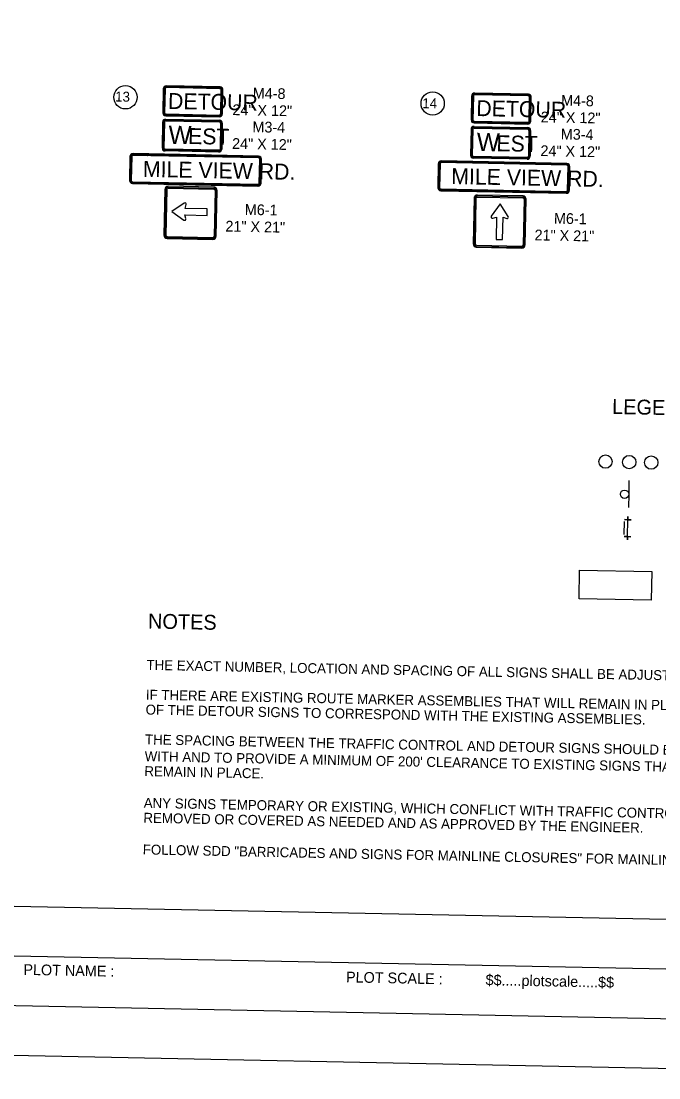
# Model space of a CAD drawing. Extents: x 299354 to 1325680, y 96128 to 228242.
# Drawn here: x 1319839 to 1323046, y 143563 to 148877 of the extents above; entities that cross this region are included whole.
import ezdxf

# ---------------------------------------------------------------- set-up
doc = ezdxf.new("R2010")
doc.units = 0
for name, color, linetype in [('CA-TEXT', 7, 'Continuous'), ('CE-TOPO-CONC-SLAB', 7, 'Continuous'), ('P_SGN_Cell', 7, 'Continuous'), ('P_TC', 7, 'Continuous'), ('PLT_Sheet_Border', 7, 'Continuous'), ('PLT_Sheet_Info', 7, 'Continuous'), ('SIGNS-POLES', 7, 'Continuous')]:
    doc.layers.add(name, color=color, linetype=linetype)

msp = doc.modelspace()

# ---------------------------------------------------------------- linework, layer by layer
at = {"layer": 'CA-TEXT'}
for centre in [(1320363.6, 148494.5), (1321908.5, 148463.4)]:
    msp.add_circle(centre, 58.6, dxfattribs=at)
at = {"layer": 'CE-TOPO-CONC-SLAB'}
for centre in [(1322777.7, 146662.3), (1322897, 146659.9), (1323007.6, 146657.6)]:
    msp.add_circle(centre, 33.5, dxfattribs=at)
at = {"layer": 'P_SGN_Cell'}
for p, q in [((1320565.7, 148384.6), (1320835.9, 148379.2)), ((1320565.9, 148380.9), (1320835.8, 148375.4)), ((1320550.6, 148369.9), (1320548, 148240)), ((1320554.4, 148369.9), (1320551.8, 148239.9)), ((1320559.4, 148369.8), (1320556.8, 148239.8)), ((1320565.8, 148375.9), (1320835.7, 148370.4)), ((1320841.8, 148364.1), (1320839.2, 148234.1)), ((1320846.8, 148364), (1320844.2, 148234)), ((1320850.6, 148363.9), (1320847.9, 148233.9)), ((1322101.4, 148333.7), (1322098.7, 148203.7)), ((1322105.1, 148333.6), (1322102.5, 148203.6)), ((1322110.1, 148333.5), (1322107.5, 148203.5)), ((1322116.5, 148348.4), (1322386.6, 148343)), ((1322116.5, 148339.6), (1322386.4, 148334.2)), ((1322116.6, 148344.6), (1322386.5, 148339.2)), ((1322392.5, 148327.8), (1322389.9, 148197.9)), ((1322397.5, 148327.7), (1322394.9, 148197.8)), ((1322401.3, 148327.7), (1322398.7, 148197.7)), ((1320832.7, 148219.2), (1320562.7, 148224.7)), ((1320832.7, 148223), (1320562.8, 148228.4)), ((1320832.8, 148228), (1320562.9, 148233.4)), ((1322383.4, 148183), (1322113.4, 148188.4)), ((1322383.5, 148186.7), (1322113.5, 148192.2)), ((1322383.6, 148191.7), (1322113.6, 148197.2)), ((1320561.8, 148031), (1320557.2, 147801.4)), ((1320566.2, 148030.9), (1320561.5, 147801.3)), ((1320571.6, 148030.8), (1320567, 147801.2)), ((1320578.3, 148037.3), (1320808, 148032.6)), ((1320578.4, 148042.7), (1320808.1, 148038.1)), ((1320808.2, 148042.5), (1320578.5, 148047.1)), ((1320814.4, 148025.9), (1320809.8, 147796.3)), ((1320819.9, 148025.8), (1320815.2, 147796.2)), ((1320819.6, 147796.1), (1320824.2, 148025.7)), ((1320659.2, 147962.1), (1320596.5, 147920.8)), ((1320663, 147935.9), (1320669.1, 147954.6)), ((1322116.5, 147986.7), (1322111.9, 147757.1)), ((1322120.9, 147986.7), (1322116.3, 147757)), ((1322126.4, 147986.5), (1322121.7, 147756.9)), ((1322133.1, 147993), (1322362.7, 147988.4)), ((1322133.2, 147998.4), (1322362.8, 147993.8)), ((1322362.9, 147998.2), (1322133.3, 148002.8)), ((1322247.2, 147957.9), (1322203.4, 147896.8)), ((1322288.6, 147895.1), (1322247.2, 147957.9)), ((1322369.1, 147981.7), (1322364.5, 147752)), ((1322374.6, 147981.5), (1322370, 147751.9)), ((1322374.4, 147751.8), (1322379, 147981.5)), ((1320596.5, 147920.8), (1320657.5, 147877)), ((1320667.6, 147884.1), (1320662.3, 147903.1)), ((1320662.3, 147903.1), (1320774.4, 147900.8)), ((1320775, 147933.6), (1320663, 147935.9)), ((1320774.4, 147900.8), (1320775, 147933.6)), ((1322210.5, 147886.7), (1322229.5, 147892)), ((1322229.5, 147892), (1322227.2, 147779.9)), ((1322260, 147779.3), (1322262.3, 147891.3)), ((1322262.3, 147891.3), (1322281.1, 147885.3)), ((1320573.4, 147794.5), (1320803.1, 147789.9)), ((1320573.2, 147784.7), (1320802.9, 147780)), ((1320573.3, 147789), (1320803, 147784.4)), ((1322128, 147740.4), (1322357.6, 147735.7)), ((1322128.1, 147744.7), (1322357.7, 147740.1)), ((1322128.2, 147750.2), (1322357.8, 147745.6)), ((1322227.2, 147779.9), (1322260, 147779.3))]:
    msp.add_line(p, q, dxfattribs=at)
for points in [[(1320553.8, 148537.1), (1320551.3, 148417.1)], [(1320557.5, 148537), (1320555.1, 148417)], [(1320562.5, 148536.9), (1320560.1, 148416.9)], [(1320838.8, 148537.6), (1320568.9, 148543)], [(1320839, 148546.3), (1320569, 148551.8)], [(1320838.9, 148542.6), (1320569, 148548)], [(1320842.5, 148411.2), (1320844.9, 148531.2)], [(1320847.5, 148411.1), (1320849.9, 148531.1)], [(1320851.3, 148411.1), (1320853.7, 148531)], [(1322104.5, 148500.8), (1322102.1, 148380.9)], [(1322108.2, 148500.8), (1322105.8, 148380.8)], [(1322113.2, 148500.7), (1322110.8, 148380.7)], [(1322389.5, 148501.3), (1322119.6, 148506.8)], [(1322389.6, 148506.3), (1322119.7, 148511.8)], [(1322389.7, 148510.1), (1322119.8, 148515.5)], [(1322393.3, 148375), (1322395.7, 148495)], [(1322398.3, 148374.9), (1322400.7, 148494.9)], [(1322402, 148374.8), (1322404.4, 148494.8)], [(1320566, 148401.8), (1320836, 148396.4)], [(1320566.1, 148405.6), (1320836.1, 148400.1)], [(1320566.2, 148410.6), (1320836.2, 148405.1)], [(1322116.8, 148369.3), (1322386.8, 148363.9)], [(1322116.8, 148365.6), (1322386.7, 148360.1)], [(1322116.9, 148374.3), (1322386.9, 148368.9)], [(1320386.3, 148196.1), (1320383.9, 148076.1)], [(1320390, 148196), (1320387.6, 148076)], [(1320395, 148195.9), (1320392.6, 148075.9)], [(1321032.8, 148189.3), (1320401.4, 148202)], [(1321032.9, 148194.3), (1320401.5, 148207)], [(1321033, 148198.1), (1320401.6, 148211)], [(1321036.5, 148063), (1321038.9, 148183)], [(1321041.5, 148062.9), (1321043.9, 148182.9)], [(1321045.2, 148062.8), (1321047.7, 148182.8)], [(1322583.5, 148153.1), (1321952.1, 148165.8)], [(1322583.6, 148158.1), (1321952.2, 148170.8)], [(1322583.7, 148161.8), (1321952.3, 148174.8)], [(1321937, 148159.9), (1321934.6, 148039.9)], [(1321940.8, 148159.8), (1321938.4, 148039.8)], [(1321945.8, 148159.7), (1321943.4, 148039.7)], [(1322587.2, 148026.7), (1322589.6, 148146.7)], [(1322592.2, 148026.6), (1322594.6, 148146.6)], [(1322596, 148026.6), (1322598.4, 148146.5)], [(1320398.6, 148064.6), (1321030, 148051.9)], [(1320398.6, 148060.8), (1321030.7, 148048.1)], [(1320398.8, 148069.6), (1321030.1, 148056.9)], [(1321949.3, 148024.6), (1322581.4, 148011.9)], [(1321949.4, 148028.3), (1322580.7, 148015.6)], [(1321949.5, 148033.3), (1322580.8, 148020.6)]]:
    msp.add_lwpolyline(points, dxfattribs=at)
for centre, radius, start, end in [((1320568.7, 148536.8), 15, 88.8468, 178.8468), ((1320568.7, 148536.8), 11.2, 88.8468, 178.8468), ((1320568.7, 148536.8), 6.25, 88.8468, 178.8468), ((1320568.7, 148536.8), 6.25, 88.8468, 96.1883), ((1320838.7, 148531.3), 6.25, 358.8468, 88.8468), ((1320838.7, 148531.3), 11.2, 358.8468, 88.8468), ((1320838.7, 148531.3), 15, 358.8468, 88.8468), ((1322119.5, 148500.5), 15, 88.8468, 178.8468), ((1322119.5, 148500.5), 11.2, 88.8468, 178.8468), ((1322119.5, 148500.5), 6.25, 88.8468, 178.8468), ((1322119.5, 148500.5), 6.25, 88.8468, 96.1883), ((1322389.4, 148495.1), 6.25, 358.8468, 88.8468), ((1322389.4, 148495.1), 11.2, 358.8468, 88.8468), ((1322389.4, 148495.1), 15, 358.8468, 88.8468), ((1320565.6, 148369.6), 15, 89.6119, 178.8462), ((1320566.3, 148416.8), 15, 178.8468, 268.8468), ((1320565.6, 148369.6), 11.2, 88.8462, 178.8462), ((1320566.3, 148416.8), 11.2, 178.8468, 268.8468), ((1320566.3, 148416.8), 6.25, 178.8468, 268.8468), ((1320835.6, 148364.2), 15, 358.8462, 88.8462), ((1320836.3, 148411.4), 15, 268.8468, 358.8468), ((1320836.3, 148411.4), 11.2, 268.8468, 358.8468), ((1320836.3, 148411.4), 6.25, 268.8468, 358.8468), ((1322117.1, 148380.6), 15, 178.8468, 268.8468), ((1322117.1, 148380.6), 11.2, 178.8468, 268.8468), ((1322117.1, 148380.6), 6.25, 178.8468, 268.8468), ((1320565.6, 148369.6), 6.25, 88.8462, 178.8462), ((1320835.6, 148364.2), 6.25, 358.8462, 88.8462), ((1320835.6, 148364.2), 11.2, 358.8462, 88.8462), ((1322116.4, 148333.4), 15, 89.6119, 178.8462), ((1322116.4, 148333.4), 11.2, 88.8462, 178.8462), ((1322116.4, 148333.4), 6.25, 88.8462, 178.8462), ((1322386.3, 148328), 6.25, 358.8462, 88.8462), ((1322386.3, 148328), 11.2, 358.8462, 88.8462), ((1322386.3, 148328), 15, 358.8462, 88.8462), ((1322387, 148375.1), 15, 268.8468, 358.8468), ((1322387, 148375.1), 11.2, 268.8468, 358.8468), ((1322387, 148375.1), 6.25, 268.8468, 358.8468), ((1320563, 148239.7), 15, 178.8462, 268.8462), ((1320563, 148239.7), 11.2, 178.8462, 268.8462), ((1320563, 148239.7), 6.25, 178.8462, 268.8462), ((1320833, 148234.2), 15, 268.8462, 358.8462), ((1320833, 148234.2), 11.2, 268.8462, 358.8462), ((1320833, 148234.2), 6.25, 268.8462, 358.8462), ((1320401.3, 148196), 15, 88.8468, 178.8468), ((1320401.3, 148195.8), 11.2, 88.8468, 178.8468), ((1320401.3, 148195.8), 6.25, 88.8468, 178.8468), ((1320475.7, 148194.3), 6.25, 88.8468, 96.1883), ((1321032.7, 148183.1), 6.25, 358.8468, 88.8468), ((1321032.7, 148183.1), 11.2, 358.8468, 88.8468), ((1321032.7, 148183.1), 15, 358.8468, 88.8468), ((1321952, 148159.7), 15, 88.8468, 178.8468), ((1321952, 148159.6), 11.2, 88.8468, 178.8468), ((1321952, 148159.6), 6.25, 88.8468, 178.8468), ((1322026.5, 148158.1), 6.25, 88.8468, 96.1883), ((1322113.7, 148203.4), 15, 178.8462, 268.8462), ((1322113.7, 148203.4), 11.2, 178.8462, 268.8462), ((1322113.7, 148203.4), 6.25, 178.8462, 268.8462), ((1322383.7, 148198), 15, 268.8462, 358.8462), ((1322383.7, 148198), 11.2, 268.8462, 358.8462), ((1322383.7, 148198), 6.25, 268.8462, 358.8462), ((1322583.4, 148146.8), 6.25, 358.8468, 88.8468), ((1322583.4, 148146.8), 11.2, 358.8468, 88.8468), ((1322583.4, 148146.8), 15, 358.8468, 88.8468), ((1320398.9, 148075.8), 15, 178.8468, 268.8468), ((1320398.9, 148075.8), 11.2, 178.8468, 268.8468), ((1320398.9, 148075.8), 6.25, 178.8468, 268.8468), ((1321030.2, 148063.1), 15, 268.8468, 358.8468), ((1321030.2, 148063.1), 11.2, 268.8468, 358.8468), ((1321030.2, 148063.1), 6.25, 268.8468, 358.8468), ((1320578.2, 148030.7), 16.4, 88.8468, 178.8468), ((1320578.2, 148030.7), 12, 88.8468, 178.8468), ((1320578.2, 148030.7), 6.56, 88.8468, 178.8468), ((1320807.8, 148026.1), 6.56, 358.8468, 88.8468), ((1320807.8, 148026.1), 12, 358.8468, 88.8468), ((1320807.8, 148026.1), 16.4, 59.4503, 88.8468), ((1320807.8, 148026.1), 16.4, 358.8468, 88.8468), ((1321949.6, 148039.6), 15, 178.8468, 268.8468), ((1321949.6, 148039.6), 11.2, 178.8468, 268.8468), ((1321949.6, 148039.6), 6.25, 178.8468, 268.8468), ((1322581, 148026.9), 15, 268.8468, 358.8468), ((1322581, 148026.9), 11.2, 268.8468, 358.8468), ((1322581, 148026.9), 6.25, 268.8468, 358.8468), ((1320662.8, 147956.7), 6.56, 342.0442, 123.3765), ((1322132.9, 147986.4), 16.4, 88.8468, 178.8468), ((1322132.9, 147986.4), 12, 88.8468, 178.8468), ((1322132.9, 147986.4), 6.56, 88.8468, 178.8468), ((1322362.6, 147981.8), 6.56, 358.8468, 88.8468), ((1322362.6, 147981.8), 12, 358.8468, 88.8468), ((1322362.6, 147981.8), 16.4, 59.4503, 88.8468), ((1322362.6, 147981.8), 16.4, 358.8468, 88.8468), ((1320661.3, 147882.3), 6.56, 234.3172, 15.6494), ((1322208.7, 147893), 6.56, 144.3172, 285.6494), ((1322283.1, 147891.5), 6.56, 252.0442, 33.3765), ((1320573.6, 147801.1), 16.4, 178.8468, 268.8468), ((1320573.6, 147801.1), 12, 178.8468, 268.8468), ((1320573.6, 147801.1), 6.56, 178.8468, 268.8468), ((1320803.2, 147796.4), 16.4, 268.8468, 358.8468), ((1320803.2, 147796.4), 12, 268.8468, 358.8468), ((1320803.2, 147796.4), 6.56, 268.8468, 358.8468), ((1322128.3, 147756.8), 16.4, 178.8468, 268.8468), ((1322128.3, 147756.8), 12, 178.8468, 268.8468), ((1322128.3, 147756.8), 6.56, 178.8468, 268.8468), ((1322357.9, 147752.2), 16.4, 268.8468, 358.8468), ((1322357.9, 147752.2), 12, 268.8468, 358.8468), ((1322357.9, 147752.2), 6.56, 268.8468, 358.8468)]:
    msp.add_arc(centre, radius, start, end, dxfattribs=at)
at = {"layer": 'P_TC'}
for p, q in [((1322871.9, 146295.4), (1322873.2, 146360.4)), ((1322890.4, 146370.1), (1322873.4, 146370.4)), ((1322873.4, 146370.4), (1322890.4, 146370.1)), ((1322888.7, 146285.1), (1322890.4, 146370.1)), ((1322890.4, 146370.1), (1322890.8, 146387.1)), ((1322890.8, 146387.1), (1322890.4, 146370.1)), ((1322890.4, 146370.1), (1322907.4, 146369.7)), ((1322907.4, 146369.7), (1322890.4, 146370.1)), ((1322888.7, 146285.1), (1322871.7, 146285.4)), ((1322871.7, 146285.4), (1322888.7, 146285.1)), ((1322888.7, 146285.1), (1322888.4, 146268.1)), ((1322888.4, 146268.1), (1322888.7, 146285.1)), ((1322905.7, 146284.8), (1322888.7, 146285.1)), ((1322888.7, 146285.1), (1322905.7, 146284.8))]:
    msp.add_line(p, q, dxfattribs=at)
msp.add_lwpolyline([(1322647.5, 146117.2), (1323011.1, 146109.8), (1323008.1, 145964.8), (1322644.6, 145972.2)], close=True, dxfattribs=at)
msp.add_lwpolyline([(1322647.5, 146117.2), (1323011.1, 146109.8), (1323008.1, 145964.8), (1322644.6, 145972.2)], close=True, dxfattribs=at)
at = {"layer": 'PLT_Sheet_Border'}
for points in [[(1308461.6, 143905.4), (1325458.1, 143563.1), (1325679.6, 154560.9), (1308683.1, 154903.2)], [(1308586.6, 144153), (1325133.2, 143819.7), (1325344.6, 154317.6), (1308798, 154650.9)]]:
    msp.add_lwpolyline(points, close=True, dxfattribs=at)
at = {"layer": 'PLT_Sheet_Info'}
for p, q in [((1309109, 144642.6), (1324855.8, 144325.4)), ((1309104, 144392.6), (1324850.8, 144075.5))]:
    msp.add_line(p, q, dxfattribs=at)
at = {"layer": 'SIGNS-POLES'}
for p, q in [((1322895.2, 146566.8), (1322894.9, 146499.3)), ((1322894.3, 146498.8), (1322893.5, 146431.3))]:
    msp.add_line(p, q, dxfattribs=at)
msp.add_circle((1322873.6, 146498.3), 20.9, dxfattribs=at)

# ---------------------------------------------------------------- texts
at = {"layer": 'CA-TEXT'}
for s, height, rotation, p in [('13', 50, 358.8468, (1320311.3, 148473.5)), ('14', 50, 358.8468, (1321855.9, 148439.9)), ('LEGEND', 75, 358.8468, (1322810.3, 146902)), ('NOTES', 75, 358.8468, (1320476.2, 145823.1)), ('THE EXACT NUMBER, LOCATION AND SPACING OF ALL SIGNS SHALL BE ADJUSTED TO FIT FIELD CONDITIONS.', 50, 358.8462, (1320468.9, 145615.4)), ('IF THERE ARE EXISTING ROUTE MARKER ASSEMBLIES THAT WILL REMAIN IN PLACE, ADJUST THE LOCATION ', 50, 358.8462, (1320465.9, 145465.5)), ('OF THE DETOUR SIGNS TO CORRESPOND WITH THE EXISTING ASSEMBLIES. ', 50, 358.8462, (1320464.4, 145390.5)), ('THE SPACING BETWEEN THE TRAFFIC CONTROL AND DETOUR SIGNS SHOULD BE ADJUSTED NOT TO CONFLICT', 50, 358.8462, (1320461.4, 145240.5)), ("WITH AND TO PROVIDE A MINIMUM OF 200' CLEARANCE TO EXISTING SIGNS THAT WILL", 50, 358.8462, (1320459.7, 145156)), ('REMAIN IN PLACE.', 50, 358.8462, (1320458.2, 145081)), ('ANY SIGNS TEMPORARY OR EXISTING, WHICH CONFLICT WITH TRAFFIC CONTROL "IN USE", SHALL BE', 50, 358.8462, (1320455, 144921.5)), ('REMOVED OR COVERED AS NEEDED AND AS APPROVED BY THE ENGINEER.', 50, 358.8462, (1320453.4, 144846.5)), ('FOLLOW SDD "BARRICADES AND SIGNS FOR MAINLINE CLOSURES" FOR MAINLINE ROAD CLOSED SIGNAGE.', 50, 358.8462, (1320450.2, 144687))]:
    msp.add_text(s, height=height, rotation=rotation, dxfattribs=at).set_placement(p)
at = {"layer": 'P_SGN_Cell'}
for s, height, rotation, p in [('M4-8', 54, 358.8468, (1321003.4, 148488.7)), ('DETOUR', 80, 358.8468, (1320576.8, 148436.4)), ('M4-8', 54, 358.8468, (1322554.1, 148452.4)), ('24" X 12"', 54, 358.8468, (1320901, 148405)), ('DETOUR', 80, 358.8468, (1322127.5, 148400.2)), ('24" X 12"', 54, 358.8468, (1322451.8, 148368.8)), ('W', 91.4, 358.8462, (1320579.2, 148260.7)), ('EST', 80, 358.8462, (1320677.8, 148259.9)), ('M3-4', 54, 358.8462, (1321001.8, 148319)), ('M3-4', 54, 358.8462, (1322552.5, 148282.8)), ('24" X 12"', 54, 358.8462, (1320899.4, 148235.3)), ('W', 91.4, 358.8462, (1322129.9, 148224.5)), ('EST', 80, 358.8462, (1322228.5, 148223.6)), ('24" X 12"', 54, 358.8462, (1322450.2, 148199.1)), ('MILE VIEW RD.', 80, 358.8468, (1320450.6, 148094.6)), ('MILE VIEW RD.', 80, 358.8468, (1322001.3, 148058.4)), ('M6-1', 54, 358.8468, (1320963.4, 147903.3)), ('M6-1', 54, 358.8468, (1322518.1, 147859.1)), ('21" X 21"', 54, 358.8468, (1320865.8, 147819.6)), ('21" X 21"', 54, 358.8468, (1322420.5, 147775.3))]:
    msp.add_text(s, height=height, rotation=rotation, dxfattribs=at).set_placement(p)
at = {"layer": 'PLT_Sheet_Info'}
for s, p in [('PLOT NAME :                      ', (1319849.9, 144081.1)), ('PLOT SCALE : ', (1321472.5, 144043.5)), ('$$.....plotscale.....$$', (1322174.3, 144029.4))]:
    msp.add_text(s, height=54, rotation=358.8462, dxfattribs=at).set_placement(p)

doc.saveas('drawing.dxf')
